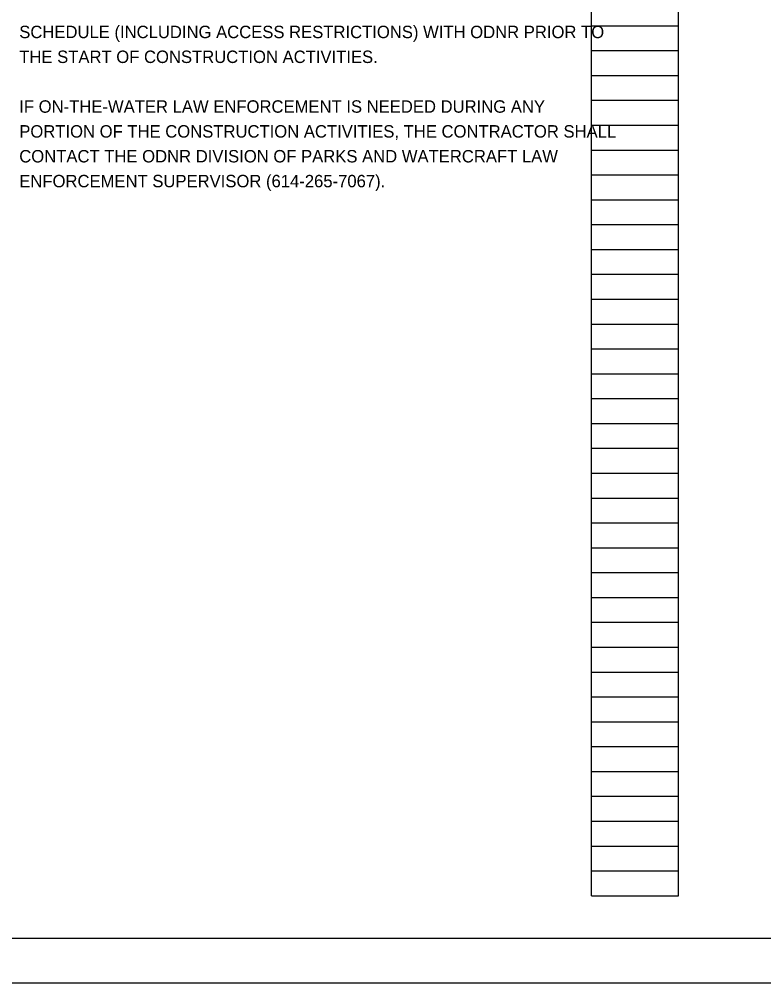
# Model space of a CAD drawing. Extents: x 0 to 34, y 0 to 22.
# Drawn here: x 17.24 to 25.62, y 0 to 10.85 of the extents above; entities that cross this region are included whole.
import ezdxf

# ---------------------------------------------------------------- set-up
doc = ezdxf.new("R2010")
doc.units = 0
for name, color, linetype in [('SH_Border', 7, 'Continuous'), ('SH_Cut_Line', 7, 'Continuous'), ('SH_Data', 7, 'Continuous'), ('SH_Text', 7, 'Continuous')]:
    doc.layers.add(name, color=color, linetype=linetype)

msp = doc.modelspace()

# ---------------------------------------------------------------- linework, layer by layer
at = {"layer": 'SH_Border'}
msp.add_lwpolyline([(1.5, 21.5), (33.5, 21.5), (33.5, 0.5), (1.5, 0.5)], close=True, dxfattribs=at)
at = {"layer": 'SH_Cut_Line'}
msp.add_lwpolyline([(0, 0), (34, 0), (34, 22), (0, 22)], close=True, dxfattribs=at)
at = {"layer": 'SH_Data'}
for p, q in [((23.68, 0.98), (23.68, 21.14)), ((24.66, 0.98), (24.66, 21.14)), ((23.68, 10.78), (24.66, 10.78)), ((23.68, 10.5), (24.66, 10.5)), ((23.68, 10.22), (24.66, 10.22)), ((23.68, 9.94), (24.66, 9.94)), ((23.68, 9.66), (24.66, 9.66)), ((23.68, 9.38), (24.66, 9.38)), ((23.68, 9.1), (24.66, 9.1)), ((23.68, 8.82), (24.66, 8.82)), ((23.68, 8.54), (24.66, 8.54)), ((23.68, 8.26), (24.66, 8.26)), ((23.68, 7.98), (24.66, 7.98)), ((23.68, 7.7), (24.66, 7.7)), ((23.68, 7.42), (24.66, 7.42)), ((23.68, 7.14), (24.66, 7.14)), ((23.68, 6.86), (24.66, 6.86)), ((23.68, 6.58), (24.66, 6.58)), ((23.68, 6.3), (24.66, 6.3)), ((23.68, 6.02), (24.66, 6.02)), ((23.68, 5.74), (24.66, 5.74)), ((23.68, 5.46), (24.66, 5.46)), ((23.68, 5.18), (24.66, 5.18)), ((23.68, 4.9), (24.66, 4.9)), ((23.68, 4.62), (24.66, 4.62)), ((23.68, 4.34), (24.66, 4.34)), ((23.68, 4.06), (24.66, 4.06)), ((23.68, 3.78), (24.66, 3.78)), ((23.68, 3.5), (24.66, 3.5)), ((23.68, 3.22), (24.66, 3.22)), ((23.68, 2.94), (24.66, 2.94)), ((23.68, 2.66), (24.66, 2.66)), ((23.68, 2.38), (24.66, 2.38)), ((23.68, 2.1), (24.66, 2.1)), ((23.68, 1.82), (24.66, 1.82)), ((23.68, 1.54), (24.66, 1.54)), ((23.68, 1.26), (24.66, 1.26)), ((23.68, 0.98), (24.66, 0.98))]:
    msp.add_line(p, q, dxfattribs=at)

# ---------------------------------------------------------------- texts
at = {"layer": 'SH_Text'}
for s, p in [('SCHEDULE (INCLUDING ACCESS RESTRICTIONS) WITH ODNR PRIOR TO ', (17.24, 10.64)), ('THE START OF CONSTRUCTION ACTIVITIES.', (17.24, 10.36)), ('IF ON-THE-WATER LAW ENFORCEMENT IS NEEDED DURING ANY ', (17.24, 9.8)), ('PORTION OF THE CONSTRUCTION ACTIVITIES, THE CONTRACTOR SHALL ', (17.24, 9.52)), ('CONTACT THE ODNR DIVISION OF PARKS AND WATERCRAFT LAW ', (17.24, 9.24)), ('ENFORCEMENT SUPERVISOR (614-265-7067).', (17.24, 8.96))]:
    msp.add_text(s, height=0.14, dxfattribs=at).set_placement(p)

doc.saveas('drawing.dxf')
